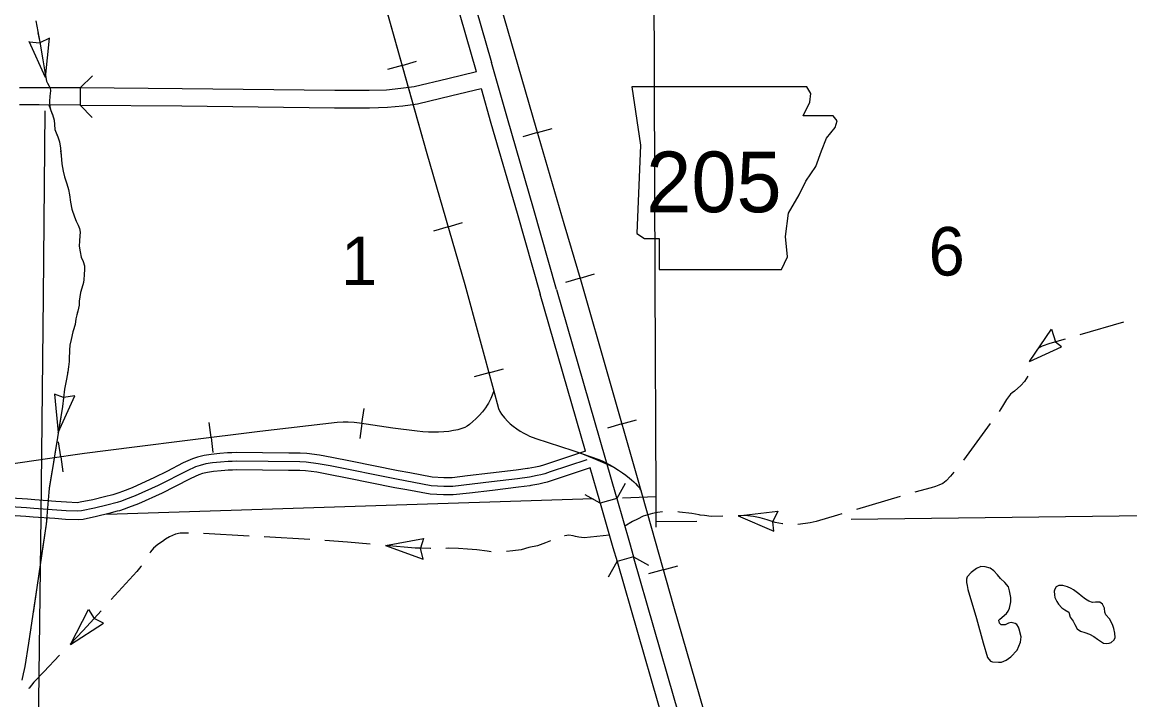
# Model space of a CAD drawing. Extents: x 1373094 to 1376427, y 1168361 to 1170494.
# Drawn here: x 1373415.5 to 1373576.1, y 1170060.2 to 1170158.6 of the extents above; entities that cross this region are included whole.
import ezdxf

# ---------------------------------------------------------------- set-up
doc = ezdxf.new("R2010")
doc.units = 0
doc.layers.add('R_Axis', color=7, linetype='Continuous')

msp = doc.modelspace()

# ---------------------------------------------------------------- linework, layer by layer
at = {"layer": 'R_Axis'}
for p, q in [((1373419.42, 1170156.23), (1373418.04, 1170155.58)), ((1373418.88, 1170150.52), (1373419.42, 1170156.22)), ((1373418.88, 1170150.52), (1373416.5, 1170155.73)), ((1373416.5, 1170155.71), (1373418.02, 1170155.58)), ((1373470.55, 1170152.29), (1373472.67, 1170152.89)), ((1373470.55, 1170152.29), (1373468.43, 1170151.7)), ((1373425.63, 1170144.73), (1373423.88, 1170146.51)), ((1373490.19, 1170142.54), (1373492.3, 1170143.15)), ((1373490.19, 1170142.54), (1373488.07, 1170141.92)), ((1373477.22, 1170128.86), (1373475.11, 1170128.25)), ((1373477.22, 1170128.86), (1373479.33, 1170129.47)), ((1373496.37, 1170121.42), (1373494.26, 1170120.8)), ((1373496.37, 1170121.42), (1373498.48, 1170122.05)), ((1373561.55, 1170109.34), (1373564.72, 1170114.04)), ((1373564.72, 1170114.04), (1373565.29, 1170112.17)), ((1373561.55, 1170109.34), (1373566.19, 1170111.47)), ((1373566.19, 1170111.47), (1373565.29, 1170112.15)), ((1373483.15, 1170107.67), (1373485.27, 1170108.26)), ((1373483.15, 1170107.67), (1373481.03, 1170107.09)), ((1373420.14, 1170104.61), (1373420.71, 1170099.01)), ((1373421.48, 1170104.09), (1373420.14, 1170104.61)), ((1373420.71, 1170099.01), (1373423.1, 1170104.33)), ((1373423.1, 1170104.33), (1373421.48, 1170104.09)), ((1373464.73, 1170100.33), (1373465.05, 1170102.51)), ((1373442.87, 1170098.31), (1373442.61, 1170100.49)), ((1373464.73, 1170100.33), (1373464.41, 1170098.15)), ((1373502.43, 1170100.27), (1373500.32, 1170099.67)), ((1373502.43, 1170100.27), (1373504.55, 1170100.88)), ((1373442.87, 1170098.31), (1373443.14, 1170096.12)), ((1373421.06, 1170095.48), (1373420.75, 1170097.66)), ((1373421.06, 1170095.48), (1373421.36, 1170093.3)), ((1373519.28, 1170086.95), (1373525.03, 1170087.64)), ((1373519.28, 1170086.95), (1373524.44, 1170084.74)), ((1373525.03, 1170087.64), (1373524.31, 1170086.1)), ((1373524.44, 1170084.74), (1373524.3, 1170086.08)), ((1373468.13, 1170082.64), (1373473.66, 1170083.63)), ((1373468.13, 1170082.64), (1373473.62, 1170080.66)), ((1373473.66, 1170083.63), (1373473.25, 1170082.26)), ((1373473.62, 1170080.66), (1373473.25, 1170082.24)), ((1373508.43, 1170079.11), (1373506.31, 1170078.51)), ((1373508.43, 1170079.11), (1373510.54, 1170079.7)), ((1373422.48, 1170068.26), (1373425.09, 1170073.35)), ((1373425.09, 1170073.35), (1373425.92, 1170072.07)), ((1373422.48, 1170068.26), (1373427.29, 1170071.36)), ((1373427.29, 1170071.36), (1373425.93, 1170072.06))]:
    msp.add_line(p, q, dxfattribs=at)
for points in [[(1373454.16, 1170269.52), (1373456.95, 1170259.94), (1373464.6, 1170232.93), (1373467.31, 1170223.27), (1373477.47, 1170186.82), (1373483.75, 1170164.69), (1373489.97, 1170143.28), (1373494.03, 1170129.36), (1373496.54, 1170120.87)], [(1373458.57, 1170240.92), (1373464.04, 1170221.42), (1373465.28, 1170217), (1373469.37, 1170202.29), (1373473.35, 1170188.39), (1373479.1, 1170168.17), (1373483.54, 1170152.71)], [(1373481.33, 1170151.35), (1373476.69, 1170167.49), (1373470.95, 1170187.7), (1373466.97, 1170201.61), (1373462.87, 1170216.33), (1373461.63, 1170220.75), (1373456.46, 1170239.2)], [(1373507.02, 1170179.18), (1373507.2, 1170120.87)], [(1373464.99, 1170172.04), (1373474.15, 1170139.51), (1373479.64, 1170120.49)], [(1373464.99, 1170172.04), (1373472.37, 1170145.82)], [(1373483.75, 1170164.69), (1373489.97, 1170143.28), (1373494.03, 1170129.36), (1373496.54, 1170120.87), (1373504.55, 1170092.86), (1373506.73, 1170085.13), (1373509.91, 1170073.82), (1373516.2, 1170052.09)], [(1373417.47, 1170158.75), (1373418.02, 1170155.63), (1373418.45, 1170153.1), (1373418.7, 1170151.62), (1373419.01, 1170150), (1373419.13, 1170149.7), (1373419.38, 1170149.27), (1373419.51, 1170148.96), (1373419.57, 1170148.59)], [(1373417.77, 1170157.03), (1373418.02, 1170155.63), (1373418.45, 1170153.1), (1373418.7, 1170151.62), (1373418.91, 1170150.53)], [(1373481.33, 1170151.35), (1373477.2, 1170150.34), (1373472.32, 1170149.18), (1373470.39, 1170148.91), (1373468.29, 1170148.71), (1373465.79, 1170148.64), (1373460.79, 1170148.63), (1373438.65, 1170148.9), (1373423.9, 1170149.01)], [(1373492.97, 1170119.78), (1373489.63, 1170131.52), (1373485.85, 1170144.57), (1373483.54, 1170152.71)], [(1373423.9, 1170149.01), (1373425.68, 1170150.76)], [(1373423.9, 1170149.01), (1373417.97, 1170149.05), (1373415.09, 1170149.05)], [(1373419.57, 1170148.59), (1373419.5, 1170147.82), (1373419.43, 1170147.04), (1373419.49, 1170146.29), (1373419.63, 1170145.75), (1373419.86, 1170145.17), (1373420.12, 1170144.36), (1373420.17, 1170143.69), (1373420.23, 1170142.99), (1373420.65, 1170141.91), (1373420.89, 1170141.18), (1373421.02, 1170140.26), (1373421.11, 1170139.21), (1373421.23, 1170138), (1373421.41, 1170136.95), (1373421.61, 1170136.1), (1373421.94, 1170135.08), (1373422.21, 1170134.29), (1373422.35, 1170133.5), (1373422.49, 1170132.45), (1373422.67, 1170131.44), (1373423.07, 1170130.31), (1373423.32, 1170129.7), (1373423.61, 1170129.1), (1373423.8, 1170128.63), (1373423.89, 1170128.08), (1373423.85, 1170127.58), (1373423.78, 1170126.85), (1373423.73, 1170126.08), (1373423.86, 1170125.23), (1373424.05, 1170124.46), (1373424.33, 1170123.85), (1373424.49, 1170123.23), (1373424.53, 1170122.73), (1373424.46, 1170121.91), (1373424.41, 1170121.21), (1373424.35, 1170120.79), (1373424.29, 1170120.43), (1373423.91, 1170119.32), (1373423.75, 1170118.08)], [(1373423.9, 1170149.01), (1373423.88, 1170146.51)], [(1373423.88, 1170146.51), (1373438.62, 1170146.4), (1373460.78, 1170146.13), (1373465.83, 1170146.14), (1373468.45, 1170146.22), (1373470.68, 1170146.43), (1373472.79, 1170146.72), (1373477.79, 1170147.91), (1373482.02, 1170148.94)], [(1373482.02, 1170148.94), (1373483.44, 1170143.88), (1373487.23, 1170130.83), (1373490.57, 1170119.1)], [(1373423.88, 1170146.51), (1373417.96, 1170146.55), (1373415.09, 1170146.55)], [(1373419.33, 1170146.54), (1373419.84, 1170145.22)], [(1373418.75, 1170145.71), (1373418.51, 1170118.77)], [(1373419.84, 1170145.22), (1373419.86, 1170145.17), (1373420.12, 1170144.36), (1373420.17, 1170143.69), (1373420.23, 1170142.99), (1373420.6, 1170142.04)], [(1373472.37, 1170145.82), (1373474.15, 1170139.51), (1373479.64, 1170120.49), (1373483.82, 1170105.22), (1373484.52, 1170102.51), (1373484.71, 1170102.06), (1373484.96, 1170101.67), (1373485.39, 1170101.14), (1373485.87, 1170100.64), (1373486.25, 1170100.27), (1373486.65, 1170099.94), (1373487.18, 1170099.55), (1373487.68, 1170099.21), (1373488.2, 1170098.91), (1373488.7, 1170098.67), (1373489.01, 1170098.52), (1373489.96, 1170098.18), (1373495.31, 1170096.42), (1373496.34, 1170096.07), (1373497.55, 1170095.61), (1373498.59, 1170095.17), (1373499.94, 1170094.6), (1373501.27, 1170093.99)], [(1373421.05, 1170139.9), (1373421.11, 1170139.21), (1373421.23, 1170138), (1373421.41, 1170136.95), (1373421.61, 1170136.1), (1373421.94, 1170135.08), (1373422.21, 1170134.29), (1373422.35, 1170133.5), (1373422.36, 1170133.46)], [(1373422.72, 1170131.29), (1373423.07, 1170130.31), (1373423.32, 1170129.7), (1373423.61, 1170129.1), (1373423.8, 1170128.63), (1373423.89, 1170128.08), (1373423.85, 1170127.58), (1373423.78, 1170126.85), (1373423.73, 1170126.08), (1373423.86, 1170125.23), (1373423.93, 1170124.94)], [(1373424.52, 1170122.83), (1373424.53, 1170122.73), (1373424.46, 1170121.91), (1373424.41, 1170121.21), (1373424.35, 1170120.79), (1373424.29, 1170120.43), (1373423.91, 1170119.32), (1373423.75, 1170118.08), (1373423.72, 1170117.49), (1373423.53, 1170116.65), (1373423.47, 1170116.35)], [(1373496.54, 1170120.87), (1373504.55, 1170092.86), (1373506.73, 1170085.13), (1373509.91, 1170073.82), (1373516.2, 1170052.09)], [(1373507.2, 1170120.87), (1373507.36, 1170089.73), (1373507.35, 1170086.12), (1373507.35, 1170085.32)], [(1373479.64, 1170120.49), (1373483.82, 1170105.22), (1373484.52, 1170102.51), (1373484.71, 1170102.06), (1373484.96, 1170101.67), (1373485.39, 1170101.14), (1373485.87, 1170100.64), (1373486.25, 1170100.27), (1373486.65, 1170099.94), (1373487.18, 1170099.55), (1373487.68, 1170099.21), (1373488.2, 1170098.91), (1373488.7, 1170098.67), (1373489.01, 1170098.52), (1373489.96, 1170098.18), (1373495.31, 1170096.42), (1373499.08, 1170095.12), (1373499.68, 1170094.85), (1373500.22, 1170094.58), (1373500.69, 1170094.33), (1373501.28, 1170093.98), (1373501.92, 1170093.57), (1373502.51, 1170093.16), (1373502.99, 1170092.82), (1373503.52, 1170092.41), (1373503.84, 1170092.16), (1373504.15, 1170091.88), (1373504.41, 1170091.62), (1373504.71, 1170091.3), (1373504.82, 1170091.16), (1373504.96, 1170090.98), (1373505.02, 1170090.89), (1373505.09, 1170090.77), (1373505.2, 1170090.57)], [(1373497.13, 1170096.31), (1373490.57, 1170119.1)], [(1373492.97, 1170119.78), (1373501.62, 1170089.76), (1373501.7, 1170089.45)], [(1373423.75, 1170118.08), (1373423.72, 1170117.49), (1373423.53, 1170116.65), (1373423.41, 1170116.12), (1373423.27, 1170115.51), (1373423.16, 1170114.69), (1373422.84, 1170113.64), (1373422.56, 1170112.5), (1373422.37, 1170111.69), (1373422.34, 1170110.99), (1373422.33, 1170110.66), (1373422.28, 1170109.95), (1373422.29, 1170109.34), (1373422.21, 1170108.55), (1373422.1, 1170107.84), (1373421.88, 1170106.75), (1373421.61, 1170105.33), (1373421.32, 1170102.78), (1373419.86, 1170093.79), (1373419.41, 1170090.93), (1373418.97, 1170085.74), (1373417.65, 1170076.89), (1373416.39, 1170068.47), (1373415.86, 1170065.1), (1373415.63, 1170064.02), (1373415.44, 1170063.1)], [(1373418.51, 1170118.77), (1373418.17, 1170086.89), (1373417.2, 1170010.35)], [(1373423.01, 1170114.2), (1373422.84, 1170113.64), (1373422.56, 1170112.5), (1373422.37, 1170111.69), (1373422.34, 1170110.99), (1373422.33, 1170110.66), (1373422.28, 1170109.95), (1373422.29, 1170109.34), (1373422.21, 1170108.55), (1373422.1, 1170107.84), (1373422.07, 1170107.7)], [(1373575.15, 1170115.03), (1373568.81, 1170113.19)], [(1373566.7, 1170112.57), (1373564.49, 1170111.93), (1373563.37, 1170111.56), (1373562.84, 1170111.25)], [(1373561.27, 1170107.18), (1373561.04, 1170106.81), (1373560.8, 1170106.42), (1373560.25, 1170105.85), (1373559.33, 1170105.02), (1373559.03, 1170104.79)], [(1373483.86, 1170105.06), (1373483.72, 1170104.69), (1373483.43, 1170103.96), (1373483.29, 1170103.66), (1373483.1, 1170103.3), (1373482.91, 1170102.98), (1373482.67, 1170102.61), (1373482.2, 1170102.01), (1373481.72, 1170101.49), (1373481.23, 1170100.99), (1373480.84, 1170100.61), (1373480.35, 1170100.18), (1373479.99, 1170099.93), (1373479.66, 1170099.76), (1373479.09, 1170099.56), (1373478.62, 1170099.43), (1373478.33, 1170099.37), (1373478.01, 1170099.3), (1373477.33, 1170099.19), (1373476.62, 1170099.11), (1373475.86, 1170099.09), (1373474.38, 1170099.1), (1373473.55, 1170099.15), (1373472.76, 1170099.21), (1373469.22, 1170099.67), (1373464.37, 1170100.38), (1373463.59, 1170100.49), (1373462.76, 1170100.54), (1373462.02, 1170100.54), (1373461.13, 1170100.48), (1373449.92, 1170099.17), (1373439.45, 1170097.89), (1373431.77, 1170096.92), (1373424.53, 1170095.96), (1373419.15, 1170095.22), (1373413.52, 1170094.41)], [(1373421.65, 1170105.54), (1373421.61, 1170105.33), (1373421.32, 1170102.78), (1373420.71, 1170099.01)], [(1373483.86, 1170105.06), (1373483.72, 1170104.69), (1373483.43, 1170103.96), (1373483.29, 1170103.66), (1373483.1, 1170103.3), (1373482.91, 1170102.98), (1373482.67, 1170102.61), (1373482.2, 1170102.01), (1373481.72, 1170101.49)], [(1373559.03, 1170104.79), (1373558.76, 1170104.59), (1373558.2, 1170103.82), (1373557.63, 1170102.85), (1373557.15, 1170102.1)], [(1373481.72, 1170101.49), (1373481.23, 1170100.99), (1373480.84, 1170100.61), (1373480.35, 1170100.18), (1373479.99, 1170099.93), (1373479.66, 1170099.76), (1373479.09, 1170099.56), (1373478.62, 1170099.43), (1373478.33, 1170099.37), (1373478.01, 1170099.3), (1373477.33, 1170099.19), (1373476.62, 1170099.11), (1373475.86, 1170099.09), (1373474.38, 1170099.1), (1373473.55, 1170099.15), (1373472.76, 1170099.21), (1373469.22, 1170099.67), (1373464.37, 1170100.38), (1373463.59, 1170100.49), (1373462.76, 1170100.54), (1373462.02, 1170100.54), (1373461.13, 1170100.48), (1373449.92, 1170099.17), (1373439.45, 1170097.89), (1373431.77, 1170096.92), (1373424.53, 1170095.96), (1373419.15, 1170095.22), (1373413.52, 1170094.41)], [(1373555.84, 1170100.34), (1373551.94, 1170095.01)], [(1373420.36, 1170096.84), (1373419.86, 1170093.79), (1373419.83, 1170093.59)], [(1373497.34, 1170095.06), (1373492.05, 1170093.3), (1373491.25, 1170093.05), (1373490.69, 1170092.9), (1373490.15, 1170092.78), (1373489.02, 1170092.57), (1373487.28, 1170092.31), (1373483.53, 1170091.87), (1373477.9, 1170091.22), (1373476.6, 1170091.22), (1373474.79, 1170091.31), (1373469.76, 1170092.24), (1373460.12, 1170094.17), (1373458.41, 1170094.49), (1373456.64, 1170094.73), (1373455.75, 1170094.76), (1373446.53, 1170094.86), (1373445.91, 1170094.83), (1373445.32, 1170094.81), (1373444.25, 1170094.73), (1373443.05, 1170094.62), (1373442.12, 1170094.48), (1373441.28, 1170094.26), (1373440.61, 1170094.03), (1373439.38, 1170093.48), (1373435.21, 1170091.36), (1373431.88, 1170089.84), (1373430.46, 1170089.3), (1373429.88, 1170089.09), (1373429.25, 1170088.89)], [(1373445.29, 1170096.06), (1373445.25, 1170096.06), (1373444.14, 1170095.98), (1373442.9, 1170095.86), (1373441.87, 1170095.71), (1373440.91, 1170095.46), (1373440.15, 1170095.19), (1373438.84, 1170094.61), (1373436.45, 1170093.39)], [(1373454.14, 1170096.03), (1373446.5, 1170096.11), (1373445.85, 1170096.08), (1373445.29, 1170096.06)], [(1373463.07, 1170094.86), (1373460.36, 1170095.4), (1373458.6, 1170095.73), (1373456.75, 1170095.97), (1373455.78, 1170096.01), (1373454.14, 1170096.03)], [(1373497.13, 1170096.31), (1373491.66, 1170094.49), (1373490.9, 1170094.25), (1373490.39, 1170094.11), (1373489.9, 1170094), (1373488.82, 1170093.8), (1373488.74, 1170093.79)], [(1373419.83, 1170093.59), (1373419.41, 1170090.93), (1373419.36, 1170090.32)], [(1373436.45, 1170093.39), (1373434.67, 1170092.48), (1373431.4, 1170091), (1373430.02, 1170090.47), (1373429.48, 1170090.27), (1373428.9, 1170090.09), (1373428.62, 1170090.01)], [(1373445.38, 1170093.56), (1373444.35, 1170093.49), (1373443.2, 1170093.38), (1373442.37, 1170093.25), (1373441.64, 1170093.06), (1373441.07, 1170092.87), (1373439.92, 1170092.36), (1373437.58, 1170091.16)], [(1373454.11, 1170093.53), (1373446.56, 1170093.61), (1373445.96, 1170093.58), (1373445.36, 1170093.56)], [(1373462.58, 1170092.4), (1373459.88, 1170092.94), (1373458.21, 1170093.26), (1373456.54, 1170093.48), (1373455.72, 1170093.51), (1373454.11, 1170093.53)], [(1373471.69, 1170093.16), (1373470, 1170093.47), (1373463.07, 1170094.86)], [(1373488.74, 1170093.79), (1373487.11, 1170093.55), (1373483.38, 1170093.11), (1373480.04, 1170092.72)], [(1373497.82, 1170093.9), (1373492.44, 1170092.12), (1373491.6, 1170091.84), (1373490.98, 1170091.68), (1373490.4, 1170091.55), (1373489.22, 1170091.33), (1373489.1, 1170091.31)], [(1373499.3, 1170088.77), (1373499.21, 1170089.07), (1373497.82, 1170093.9)], [(1373501.27, 1170093.99), (1373501.92, 1170093.57), (1373502.51, 1170093.16), (1373502.99, 1170092.82), (1373503.52, 1170092.41), (1373503.84, 1170092.16), (1373504.15, 1170091.88), (1373504.41, 1170091.62), (1373504.71, 1170091.3), (1373504.82, 1170091.16), (1373504.96, 1170090.98), (1373505.02, 1170090.89), (1373505.09, 1170090.77), (1373505.2, 1170090.57)], [(1373471.23, 1170090.7), (1373469.53, 1170091.01), (1373462.58, 1170092.4)], [(1373480.04, 1170092.72), (1373477.83, 1170092.47), (1373476.63, 1170092.47), (1373474.93, 1170092.55), (1373471.69, 1170093.16)], [(1373550.57, 1170093.29), (1373550.07, 1170092.69), (1373549.44, 1170092.04), (1373548.98, 1170091.65), (1373548.38, 1170091.37), (1373547.88, 1170091.2), (1373547.29, 1170091), (1373544.88, 1170090.35)], [(1373437.58, 1170091.16), (1373435.75, 1170090.23), (1373432.36, 1170088.69), (1373430.9, 1170088.13), (1373430.28, 1170087.9), (1373429.6, 1170087.69), (1373429.27, 1170087.6)], [(1373480.32, 1170090.24), (1373477.98, 1170089.97), (1373476.58, 1170089.97), (1373474.64, 1170090.06), (1373471.23, 1170090.7)], [(1373489.1, 1170091.31), (1373487.44, 1170091.08), (1373483.67, 1170090.62), (1373480.32, 1170090.24)], [(1373502.92, 1170091.64), (1373501.7, 1170089.45)], [(1373420.37, 1170089.02), (1373417.29, 1170089.24), (1373416.23, 1170089.36), (1373413.86, 1170089.49), (1373412.49, 1170089.58), (1373411.99, 1170089.61), (1373411.59, 1170089.64)], [(1373429.25, 1170088.89), (1373427.74, 1170088.48), (1373425.98, 1170088.05), (1373424.1, 1170087.67), (1373423.54, 1170087.6), (1373421.84, 1170087.67), (1373417.17, 1170087.99), (1373416.12, 1170088.11), (1373413.79, 1170088.24)], [(1373428.62, 1170090.01), (1373427.42, 1170089.69), (1373425.71, 1170089.27), (1373423.9, 1170088.9), (1373423.49, 1170088.85), (1373421.91, 1170088.91), (1373420.37, 1170089.02)], [(1373427.74, 1170087.19), (1373498.24, 1170089.44)], [(1373499.3, 1170088.77), (1373497.12, 1170089.98)], [(1373501.7, 1170089.45), (1373499.3, 1170088.77)], [(1373499.3, 1170088.77), (1373501.13, 1170082.37), (1373501.72, 1170080.3)], [(1373501.7, 1170089.45), (1373503.53, 1170083.06), (1373504.13, 1170080.99)], [(1373502.54, 1170089.57), (1373507.36, 1170089.73)], [(1373542.76, 1170089.74), (1373536.44, 1170087.87)], [(1373420.2, 1170086.53), (1373417.06, 1170086.75), (1373416.02, 1170086.86), (1373413.71, 1170086.99), (1373412.32, 1170087.09), (1373411.82, 1170087.12), (1373411.43, 1170087.14)], [(1373429.27, 1170087.6), (1373428.05, 1170087.27), (1373426.26, 1170086.83), (1373424.3, 1170086.43), (1373423.59, 1170086.35), (1373421.77, 1170086.42), (1373420.2, 1170086.53)], [(1373508.34, 1170087.54), (1373507.58, 1170087.43), (1373506.87, 1170087.26), (1373506.19, 1170087.09), (1373505.53, 1170086.87), (1373504.68, 1170086.47), (1373503.97, 1170086.12), (1373502.85, 1170085.44)], [(1373513.8, 1170087.06), (1373513.61, 1170087.09), (1373512.55, 1170087.29), (1373510.8, 1170087.49), (1373510.53, 1170087.51)], [(1373517.08, 1170086.9), (1373515.38, 1170086.85), (1373514.39, 1170086.97), (1373513.8, 1170087.06)], [(1373525.74, 1170085.77), (1373525.72, 1170085.77), (1373524.67, 1170085.98), (1373523.48, 1170086.34), (1373522.47, 1170086.64), (1373521.53, 1170086.83), (1373520.23, 1170086.98), (1373519.28, 1170086.95)], [(1373534.33, 1170087.24), (1373533.67, 1170087.05), (1373530.62, 1170086.14), (1373529.73, 1170085.93), (1373529.07, 1170085.84), (1373527.93, 1170085.66)], [(1373535.69, 1170086.46), (1373590.11, 1170087.11), (1373616.48, 1170087.11)], [(1373419.04, 1170086.61), (1373418.97, 1170085.74), (1373418.35, 1170081.58)], [(1373507.35, 1170086.12), (1373513.29, 1170086.19)], [(1373439.6, 1170084.43), (1373438.4, 1170084.43), (1373437.69, 1170084.26), (1373436.86, 1170083.88), (1373436.25, 1170083.56), (1373435.84, 1170083.23), (1373435.14, 1170082.78), (1373434.53, 1170082.26), (1373434.08, 1170081.73), (1373433.98, 1170081.54)], [(1373448.38, 1170084), (1373441.79, 1170084.37)], [(1373457.17, 1170083.51), (1373450.58, 1170083.88)], [(1373500.62, 1170084.14), (1373496.97, 1170083.77), (1373496.19, 1170083.86), (1373495.72, 1170083.96), (1373495.34, 1170084.04), (1373494.72, 1170084.13), (1373494.16, 1170084.03), (1373494.13, 1170084.03)], [(1373462.65, 1170083.1), (1373459.37, 1170083.38)], [(1373465.94, 1170082.82), (1373462.65, 1170083.1)], [(1373474.72, 1170082.21), (1373474.67, 1170082.21), (1373473.3, 1170082.25), (1373472.47, 1170082.27), (1373468.13, 1170082.64)], [(1373483.49, 1170081.71), (1373482.88, 1170081.82), (1373481.39, 1170082.03), (1373480.02, 1170082.1), (1373478.74, 1170082.2), (1373477.36, 1170082.24), (1373476.92, 1170082.22)], [(1373492.06, 1170083.29), (1373491.34, 1170083.01), (1373490.19, 1170082.58), (1373488.95, 1170082.34), (1373487.81, 1170082.02), (1373486.64, 1170081.87), (1373485.68, 1170081.75)], [(1373504.13, 1170080.99), (1373501.72, 1170080.3)], [(1373521.63, 1170020.5), (1373521.34, 1170021.4), (1373521.24, 1170021.77), (1373510.03, 1170060.5), (1373504.13, 1170080.99)], [(1373504.13, 1170080.99), (1373506.31, 1170079.79)], [(1373418.03, 1170079.41), (1373417.65, 1170076.89), (1373417.05, 1170072.88)], [(1373432.8, 1170079.69), (1373432.69, 1170079.57), (1373432.1, 1170078.86), (1373428.39, 1170074.78)], [(1373500.51, 1170078.11), (1373501.72, 1170080.3)], [(1373501.72, 1170080.3), (1373507.63, 1170059.81), (1373518.51, 1170022.21)], [(1373552.5, 1170078.07), (1373552.4, 1170077.75), (1373552.41, 1170077.28), (1373552.47, 1170076.85), (1373552.61, 1170076.25), (1373553.86, 1170072.05), (1373554.82, 1170068.54), (1373555.46, 1170066.39), (1373555.85, 1170065.88), (1373556.15, 1170065.76), (1373557.02, 1170065.7), (1373557.48, 1170065.73), (1373558.14, 1170066), (1373558.81, 1170066.47), (1373559.76, 1170067.45), (1373560.21, 1170068.6), (1373560.3, 1170069.41), (1373560.03, 1170070.5), (1373559.91, 1170070.78), (1373559.68, 1170071.18), (1373559.46, 1170071.32), (1373558.89, 1170071.47), (1373558.46, 1170071.39), (1373557.98, 1170071.11), (1373557.42, 1170071.14), (1373557.19, 1170071.38), (1373557.08, 1170071.81), (1373557.23, 1170071.97), (1373558.17, 1170072.77), (1373558.44, 1170073.11), (1373558.63, 1170073.55), (1373558.8, 1170074.45), (1373558.83, 1170075.11), (1373558.65, 1170076.07), (1373558.48, 1170076.63), (1373557.93, 1170077.25), (1373557.33, 1170077.85), (1373556.88, 1170078.39), (1373556.35, 1170078.96), (1373555.81, 1170079.36), (1373555.12, 1170079.55), (1373554.49, 1170079.57), (1373553.83, 1170079.28), (1373553.05, 1170078.74), (1373552.5, 1170078.07)], [(1373565.12, 1170076.01), (1373565.16, 1170075.47), (1373565.22, 1170075.08), (1373565.47, 1170074.51), (1373565.71, 1170074.15), (1373566.23, 1170073.58), (1373566.65, 1170073.29), (1373567.21, 1170072.96), (1373567.41, 1170072.24), (1373567.85, 1170071.67), (1373568.08, 1170071.16), (1373568.45, 1170070.56), (1373568.91, 1170070.2), (1373569.53, 1170070), (1373570.23, 1170069.78), (1373570.86, 1170069.44), (1373571.37, 1170069.04), (1373571.83, 1170068.74), (1373572.28, 1170068.49), (1373572.64, 1170068.41), (1373573.08, 1170068.46), (1373573.38, 1170068.57), (1373573.79, 1170068.93), (1373573.97, 1170069.29), (1373573.91, 1170069.9), (1373573.77, 1170070.58), (1373573.58, 1170071.18), (1373573.14, 1170071.98), (1373572.59, 1170072.57), (1373572.45, 1170072.98), (1373572.38, 1170073.55), (1373572.12, 1170074.12), (1373571.72, 1170074.43), (1373571.08, 1170074.41), (1373570.66, 1170074.38), (1373570.11, 1170074.58), (1373569.65, 1170074.87), (1373569.02, 1170075.32), (1373568.66, 1170075.64), (1373568.29, 1170075.93), (1373567.93, 1170076.22), (1373567.59, 1170076.42), (1373567.05, 1170076.64), (1373566.38, 1170076.82), (1373565.8, 1170076.85), (1373565.39, 1170076.62), (1373565.2, 1170076.32), (1373565.12, 1170076.01)], [(1373426.91, 1170073.15), (1373424.32, 1170070.3), (1373422.43, 1170068.31)], [(1373416.73, 1170070.7), (1373416.39, 1170068.47), (1373415.86, 1170065.1), (1373415.67, 1170064.19)], [(1373420.91, 1170066.72), (1373418.63, 1170064.33)], [(1373418.63, 1170064.33), (1373417.18, 1170062.8), (1373416.51, 1170061.96), (1373416.4, 1170061.91)]]:
    msp.add_lwpolyline(points, dxfattribs=at)
msp.add_lwpolyline([(1373503.88, 1170149.18), (1373505.15, 1170140.72), (1373504.59, 1170127.89), (1373505.71, 1170127.19), (1373507.83, 1170127.19), (1373507.83, 1170122.68), (1373525.59, 1170122.68), (1373526.44, 1170124.51), (1373526.16, 1170127.47), (1373526.58, 1170130.86), (1373528.13, 1170133.53), (1373529.12, 1170135.51), (1373530.53, 1170137.62), (1373531.37, 1170139.88), (1373532.08, 1170141.71), (1373533.35, 1170143.26), (1373533.63, 1170144.25), (1373533.07, 1170144.95), (1373528.69, 1170144.95), (1373529.68, 1170146.93), (1373529.82, 1170148.2), (1373529.24, 1170149.17)], close=True, dxfattribs=at)

# ---------------------------------------------------------------- texts
for s, height, p in [('205', 8.8, (1373505.95, 1170130.98)), ('6', 7.04, (1373546.9, 1170121.8)), ('1', 7.04, (1373461.73, 1170120.41))]:
    msp.add_text(s, height=height, dxfattribs=at).set_placement(p)

doc.saveas('drawing.dxf')
